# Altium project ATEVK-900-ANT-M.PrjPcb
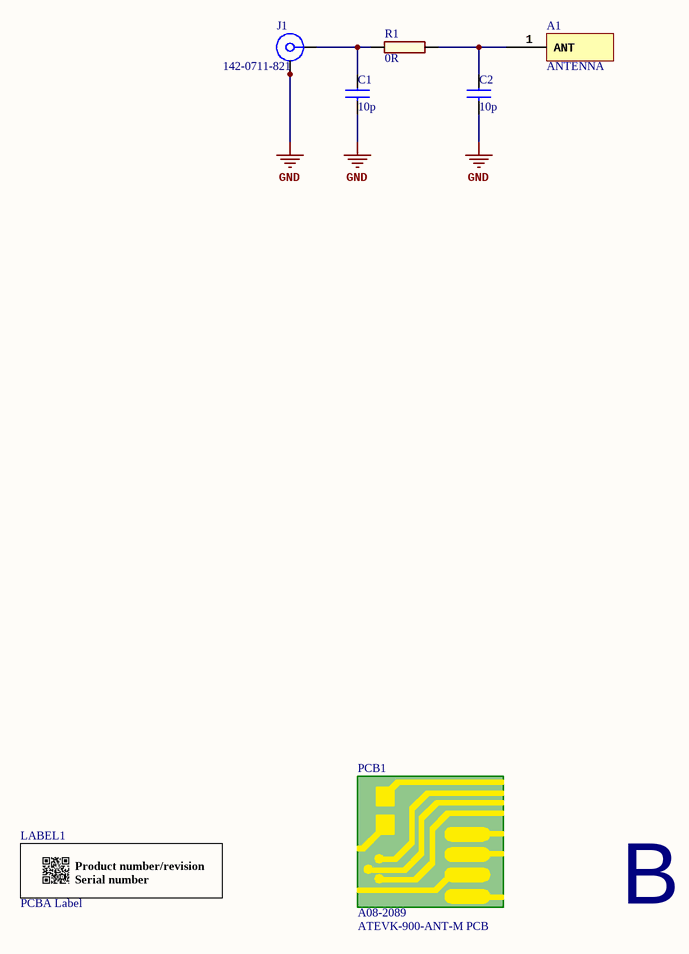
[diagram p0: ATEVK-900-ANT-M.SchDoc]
1 sheet, 7 parts. Net scope: global (net labels, ports and power ports of the same name join across sheets).
Board file: ATEVK-900-ANT-M.PcbDoc

## Sheet ATEVK-900-ANT-M.SchDoc: ATEVK-900-ANT-M
size A3; Organization: ATMEL INDIA; Address1: CHENNAI; Address3: INDIA; Revision: 1; SheetNumber: 1; SheetTotal: 1; CheckedBy: SY; DrawnBy: OJS; PageSetup: Record=PageOptions|CenterHorizontal=True|CenterVertical=True|PrintScale=0.73|XCorrection=1.00|YCorrection=1.00|PrintKind=1|BorderSize=5000000|LeftOffset=0|BottomOffset=0|Orientation=2|PaperLength=1000|PaperWidth=1000|Scale=100|PaperSource=7|PrintQuality=-4|MediaType=1|DitherType=10|PaperKind=Letter|PrintScaleMode=1

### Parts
A1  ANTENNA
C1  value 10p  [AP1-00001]  (hidden comment: CAP-NONPOL)
C2  value 10p  [AP1-00001]  (hidden comment: CAP-NONPOL)
J1  value 142-0711-821  [AP8-00443]  (hidden comment: Board Edge Mounting)
LABEL1  value PCBA Label  [AP8-00317]  (hidden comment: PCBA_LABEL)
PCB1  value ATEVK-900-ANT-M PCB  AN: A08-2089  (hidden comment: PCB)  (mechanical)
R1  value 0R  [AP2-00000]  (hidden comment: R2)

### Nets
GND: C1.2 C2.2 J1.2 J1.2.1
NetA1_1: A1.1(ANT) C2.1 R1.2
NetC1_1: C1.1 J1.1 R1.1

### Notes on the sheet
- B

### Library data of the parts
C1 C2 = A01-0015: Ceramic capacitor, SMD 0402, NP0, 50V, +/-5%; PartGroup: Capacitors,Ceramic,SMD 0402; TemperatureRange: -55 - +125 deg C; ComponentStatus: 'Active (verified)'
J1 = A08-1047: End Launch Jack Receptacle, Round Contact (de21535); Manufacturer: EMERSON; PartGroup: Mechanical devices,Connectors,Coaxial; Art.-Nr.: 21535; ComponentStatus: 'Active (verified)'
LABEL1 = A09-0611: PCBA identification label PP Top White Gloss; PartGroup: Mechanical devices,Packaging materials,Printed Labels; Manufacturer: ACT Logimark AS; MPN: 505462; ComponentStatus: 'Active (verified)'
PCB1 = A08-2089: ATEVK-900-ANT-M PCB; PartGroup: Mechanical devices,Printed circuit boards; ComponentStatus: 'New (not verified)'
R1 = A02-0163: RES 0.0 OHM 1/16W 0402 SMD; PartGroup: Resistors,SMD,0402 1%; Manufacturer: (n/a); MPN: RMCF0402ZT0R00; Tolerance: 1 %; TemperatureRange: -55 - +125 deg C; ComponentStatus: 'Active (verified)'

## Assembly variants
ATEVK-900-ANT-M Tuned: not fitted C1 C2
